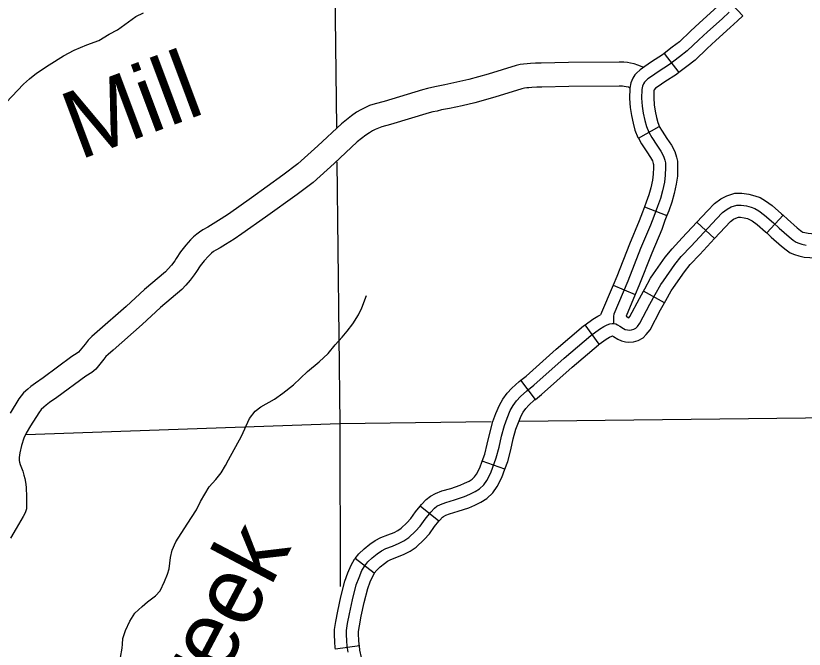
# Model space of a CAD drawing. Extents: x -3711 to 825, y -151 to 1050.
# Drawn here: x -2798.1 to -2743.1, y 424.3 to 468.5 of the extents above; entities that cross this region are included whole.
import ezdxf

# ---------------------------------------------------------------- set-up
doc = ezdxf.new("R2010")
doc.units = 0
for name, color, linetype in [('Level 32', 7, 'Continuous'), ('Level 35', 7, 'Continuous'), ('Level 46', 7, 'Continuous'), ('Level 5', 7, 'Continuous')]:
    doc.layers.add(name, color=color, linetype=linetype)

msp = doc.modelspace()

# ---------------------------------------------------------------- linework, layer by layer
at = {"layer": 'Level 32'}
for p, q in [((-2748.496, 469.762), (-2747.349, 468.533)), ((-2752.858, 465.892), (-2751.836, 464.557)), ((-2754.647, 459.97), (-2753.188, 460.804)), ((-2754.23, 455.177), (-2752.658, 454.58)), ((-2745.687, 453.356), (-2744.543, 454.589)), ((-2749.334, 452.961), (-2750.566, 454.106)), ((-2756.417, 449.713), (-2754.868, 449.059)), ((-2752.83, 448.472), (-2754.301, 449.286)), ((-2757.38, 445.58), (-2758.374, 446.936)), ((-2761.846, 441.723), (-2762.864, 443.061)), ((-2763.971, 436.847), (-2765.553, 437.414)), ((-2768.576, 433.207), (-2769.889, 434.257)), ((-2773.097, 429.573), (-2774.419, 430.611)), ((-2774.134, 424.501), (-2775.798, 424.263))]:
    msp.add_line(p, q, dxfattribs=at)
for points in [[(-2748.496, 469.762), (-2748.874, 469.409), (-2749.379, 468.944), (-2750.388, 468.032), (-2751.002, 467.459), (-2751.786, 466.714), (-2752.288, 466.327), (-2752.858, 465.892)], [(-2748.302, 468.792), (-2748.812, 468.323), (-2749.819, 467.413), (-2750.425, 466.847), (-2751.239, 466.074), (-2751.776, 465.661), (-2752.48, 465.123), (-2753.265, 464.612), (-2753.734, 464.295), (-2753.996, 464.115), (-2754.175, 463.936), (-2754.225, 463.881), (-2754.299, 463.77), (-2754.368, 463.605), (-2754.41, 463.384), (-2754.423, 462.777), (-2754.382, 462.212), (-2754.313, 461.715), (-2754.203, 461.218), (-2754.093, 460.804), (-2753.927, 460.404), (-2753.707, 460.018), (-2753.362, 459.494), (-2753.072, 459.066), (-2752.893, 458.721), (-2752.797, 458.431), (-2752.763, 458.253), (-2752.748, 458.076), (-2752.748, 457.921), (-2752.769, 457.397), (-2752.838, 456.9), (-2752.962, 456.307), (-2753.114, 455.769), (-2753.321, 455.203), (-2753.582, 454.513), (-2753.803, 453.892), (-2754.492, 452.264), (-2755.388, 449.988), (-2756.367, 447.67), (-2756.395, 447.532), (-2756.395, 447.353), (-2756.396, 447.024)], [(-2747.349, 468.533), (-2747.731, 468.176), (-2748.246, 467.702), (-2749.25, 466.794), (-2749.849, 466.235), (-2750.692, 465.435), (-2751.265, 464.994), (-2751.836, 464.557)], [(-2752.858, 465.892), (-2752.965, 465.81), (-2753.73, 465.313), (-2754.207, 464.99), (-2754.535, 464.765), (-2754.786, 464.514), (-2754.889, 464.399), (-2755.043, 464.172), (-2755.178, 463.847), (-2755.249, 463.472), (-2755.265, 462.756), (-2755.218, 462.123), (-2755.141, 461.566), (-2755.02, 461.019), (-2754.891, 460.534), (-2754.684, 460.034), (-2754.648, 459.971)], [(-2751.836, 464.557), (-2751.994, 464.435), (-2752.801, 463.911), (-2753.261, 463.6), (-2753.457, 463.466), (-2753.558, 463.365), (-2753.558, 463.363), (-2753.571, 463.297), (-2753.582, 462.798), (-2753.546, 462.3), (-2753.485, 461.864), (-2753.386, 461.418), (-2753.295, 461.074), (-2753.171, 460.775), (-2753.187, 460.804)], [(-2753.188, 460.804), (-2752.99, 460.458), (-2752.663, 459.96), (-2752.349, 459.497), (-2752.117, 459.05), (-2751.981, 458.643), (-2751.929, 458.367), (-2751.908, 458.111), (-2751.908, 457.904), (-2751.931, 457.322), (-2752.009, 456.756), (-2752.145, 456.106), (-2752.313, 455.51), (-2752.533, 454.909), (-2752.658, 454.58)], [(-2754.647, 459.97), (-2754.423, 459.578), (-2754.061, 459.027), (-2753.796, 458.635), (-2753.67, 458.392), (-2753.612, 458.219), (-2753.597, 458.14), (-2753.589, 458.041), (-2753.589, 457.938), (-2753.607, 457.471), (-2753.667, 457.044), (-2753.779, 456.507), (-2753.914, 456.027), (-2754.108, 455.497), (-2754.23, 455.177)], [(-2750.566, 454.106), (-2749.817, 454.912), (-2749.341, 455.412), (-2748.902, 455.735), (-2748.485, 455.959), (-2747.909, 456.129), (-2747.428, 456.129), (-2746.943, 456.072), (-2746.517, 455.958), (-2746.158, 455.827), (-2745.771, 455.589), (-2745.319, 455.263), (-2744.661, 454.698), (-2744.543, 454.589)], [(-2754.23, 455.177), (-2754.372, 454.803), (-2754.587, 454.197), (-2755.271, 452.582), (-2756.167, 450.305), (-2756.417, 449.713)], [(-2750.974, 452.431), (-2749.204, 454.336), (-2748.783, 454.779), (-2748.452, 455.023), (-2748.164, 455.178), (-2747.788, 455.288), (-2747.478, 455.288), (-2747.102, 455.244), (-2746.77, 455.155), (-2746.526, 455.067), (-2746.239, 454.89), (-2745.84, 454.602), (-2745.221, 454.07), (-2744.813, 453.692)], [(-2752.658, 454.58), (-2752.793, 454.223), (-2753.019, 453.587), (-2753.714, 451.946), (-2754.61, 449.67), (-2754.868, 449.059)], [(-2749.334, 452.961), (-2748.591, 453.76), (-2748.226, 454.146), (-2748.001, 454.31), (-2747.842, 454.396), (-2747.666, 454.448), (-2747.527, 454.448), (-2747.26, 454.416), (-2747.022, 454.353), (-2746.894, 454.306), (-2746.706, 454.19), (-2746.361, 453.941), (-2745.78, 453.443), (-2745.687, 453.356)], [(-2744.543, 454.589), (-2744.249, 454.315), (-2743.566, 453.711), (-2743.333, 453.519), (-2743.229, 453.45), (-2743.16, 453.419), (-2743.036, 453.381), (-2742.806, 453.332), (-2742.563, 453.306), (-2742.247, 453.291), (-2741.5, 453.26), (-2741.159, 453.26), (-2740.799, 453.217), (-2740.495, 453.156), (-2740.194, 453.076), (-2739.826, 452.947), (-2739.442, 452.801), (-2739.401, 452.781)], [(-2754.301, 449.286), (-2754.209, 449.452), (-2753.794, 450.191), (-2753.593, 450.493), (-2752.775, 451.652), (-2752.296, 452.252), (-2751.589, 453.005), (-2750.566, 454.106)], [(-2744.813, 453.692), (-2744.112, 453.072), (-2743.834, 452.843), (-2743.639, 452.713), (-2743.459, 452.631), (-2743.247, 452.566), (-2742.937, 452.501)], [(-2745.687, 453.356), (-2745.378, 453.069), (-2744.658, 452.433), (-2744.336, 452.168), (-2744.049, 451.976), (-2743.758, 451.844), (-2743.458, 451.751), (-2743.068, 451.669), (-2742.691, 451.629), (-2742.322, 451.612), (-2741.536, 451.578), (-2741.257, 451.578), (-2741.062, 451.555), (-2740.877, 451.518), (-2740.689, 451.468), (-2740.404, 451.368), (-2740.103, 451.253), (-2740.121, 451.262)], [(-2752.83, 448.472), (-2752.741, 448.634), (-2752.359, 449.312), (-2752.206, 449.542), (-2751.431, 450.642), (-2751.025, 451.15), (-2750.36, 451.858), (-2749.334, 452.961)], [(-2774.92, 424.06), (-2774.979, 424.474), (-2775.019, 424.849), (-2775.038, 425.282), (-2775.038, 425.578), (-2774.96, 426.051), (-2774.822, 426.741), (-2774.605, 427.727), (-2774.349, 428.771), (-2774.152, 429.284), (-2773.955, 429.757), (-2773.758, 430.092), (-2773.541, 430.368), (-2773.246, 430.644), (-2772.891, 430.94), (-2772.596, 431.137), (-2772.281, 431.294), (-2771.828, 431.472), (-2771.355, 431.669), (-2771.02, 431.846), (-2770.685, 432.063), (-2770.212, 432.516), (-2769.897, 432.871), (-2769.543, 433.344), (-2769.149, 433.837), (-2768.893, 434.113), (-2768.716, 434.251), (-2768.459, 434.389), (-2768.105, 434.527), (-2767.494, 434.704), (-2766.785, 434.941), (-2766.431, 435.099), (-2766.056, 435.276), (-2765.741, 435.473), (-2765.446, 435.749), (-2765.229, 436.065), (-2764.953, 436.597), (-2764.579, 437.642), (-2764.382, 438.391), (-2764.205, 439.159), (-2764.008, 439.908), (-2763.811, 440.421), (-2763.594, 440.953), (-2763.397, 441.288), (-2763.161, 441.623), (-2762.885, 441.919), (-2762.432, 442.333), (-2761.94, 442.707), (-2759.832, 444.6), (-2757.961, 446.196), (-2757.37, 446.63), (-2757.072, 446.809), (-2756.834, 446.923), (-2756.64, 446.994), (-2756.49, 447.021), (-2756.396, 447.024), (-2756.234, 446.994), (-2756.11, 446.932), (-2755.951, 446.835), (-2755.695, 446.676), (-2755.563, 446.614), (-2755.413, 446.579), (-2755.298, 446.57), (-2755.139, 446.579), (-2754.98, 446.623), (-2754.839, 446.703), (-2754.724, 446.817), (-2754.539, 447.047), (-2753.841, 448.381), (-2753.475, 449.043), (-2753.077, 449.752), (-2752.9, 450.018), (-2752.103, 451.147), (-2751.66, 451.701), (-2750.974, 452.431)], [(-2756.417, 449.713), (-2757.295, 447.634)], [(-2755.506, 447.548), (-2755.312, 447.428), (-2755.245, 447.51), (-2754.581, 448.779), (-2754.301, 449.286)], [(-2754.868, 449.059), (-2755.506, 447.548)], [(-2757.38, 445.58), (-2756.904, 445.929), (-2756.673, 446.068), (-2756.507, 446.148), (-2756.464, 446.163), (-2756.392, 446.119), (-2756.096, 445.936), (-2755.84, 445.816), (-2755.542, 445.746), (-2755.307, 445.728), (-2755.001, 445.745), (-2754.656, 445.84), (-2754.326, 446.027), (-2754.098, 446.255), (-2753.832, 446.584), (-2753.101, 447.983), (-2752.83, 448.472)], [(-2758.374, 446.936), (-2757.836, 447.331), (-2757.472, 447.549), (-2757.295, 447.634)], [(-2762.864, 443.061), (-2762.476, 443.356), (-2760.386, 445.232), (-2758.483, 446.856), (-2758.374, 446.936)], [(-2761.846, 441.723), (-2761.404, 442.059), (-2759.278, 443.967), (-2757.439, 445.537), (-2757.38, 445.58)], [(-2765.553, 437.414), (-2765.383, 437.891), (-2765.198, 438.592), (-2765.021, 439.361), (-2764.809, 440.167), (-2764.593, 440.73), (-2764.35, 441.327), (-2764.104, 441.744), (-2763.815, 442.155), (-2763.477, 442.517), (-2762.971, 442.979), (-2762.864, 443.061)], [(-2763.971, 436.847), (-2763.775, 437.392), (-2763.566, 438.189), (-2763.389, 438.958), (-2763.207, 439.65), (-2763.029, 440.112), (-2762.839, 440.58), (-2762.69, 440.832), (-2762.507, 441.092), (-2762.293, 441.321), (-2761.893, 441.687), (-2761.846, 441.723)], [(-2769.889, 434.257), (-2769.786, 434.386), (-2769.463, 434.735), (-2769.176, 434.958), (-2768.813, 435.154), (-2768.375, 435.324), (-2767.745, 435.507), (-2767.09, 435.726), (-2766.782, 435.863), (-2766.461, 436.015), (-2766.256, 436.143), (-2766.087, 436.301), (-2765.951, 436.498), (-2765.726, 436.933), (-2765.553, 437.414)], [(-2768.576, 433.207), (-2768.512, 433.288), (-2768.323, 433.492), (-2768.255, 433.544), (-2768.106, 433.624), (-2767.835, 433.73), (-2767.244, 433.902), (-2766.481, 434.156), (-2766.08, 434.335), (-2765.652, 434.537), (-2765.227, 434.804), (-2764.805, 435.198), (-2764.507, 435.632), (-2764.181, 436.26), (-2763.971, 436.847)], [(-2774.419, 430.611), (-2774.162, 430.938), (-2773.802, 431.274), (-2773.395, 431.614), (-2773.019, 431.865), (-2772.623, 432.063), (-2772.143, 432.251), (-2771.714, 432.43), (-2771.446, 432.572), (-2771.209, 432.725), (-2770.819, 433.1), (-2770.549, 433.403), (-2770.208, 433.859), (-2769.889, 434.257)], [(-2773.097, 429.573), (-2772.92, 429.798), (-2772.689, 430.013), (-2772.387, 430.265), (-2772.173, 430.408), (-2771.939, 430.526), (-2771.513, 430.692), (-2770.996, 430.908), (-2770.594, 431.121), (-2770.161, 431.401), (-2769.606, 431.933), (-2769.246, 432.339), (-2768.878, 432.83), (-2768.576, 433.207)], [(-2775.798, 424.263), (-2775.814, 424.371), (-2775.857, 424.786), (-2775.879, 425.263), (-2775.879, 425.647), (-2775.786, 426.202), (-2775.644, 426.914), (-2775.424, 427.917), (-2775.153, 429.023), (-2774.932, 429.596), (-2774.709, 430.133), (-2774.461, 430.555), (-2774.436, 430.589)], [(-2774.134, 424.501), (-2774.145, 424.577), (-2774.18, 424.912), (-2774.198, 425.301), (-2774.198, 425.508), (-2774.133, 425.9), (-2773.999, 426.568), (-2773.786, 427.536), (-2773.545, 428.519), (-2773.371, 428.971), (-2773.201, 429.381), (-2773.055, 429.629), (-2773.08, 429.595)], [(-2773.604, 418.386), (-2773.499, 418.73), (-2773.368, 419.254), (-2773.28, 419.761), (-2773.211, 420.363), (-2773.234, 420.921), (-2773.28, 421.446), (-2773.399, 421.996), (-2773.556, 422.467), (-2773.867, 423.304), (-2773.987, 423.696), (-2774.092, 424.205), (-2774.134, 424.501)]]:
    msp.add_lwpolyline(points, dxfattribs=at)
at = {"layer": 'Level 35'}
for points in [[(-2798.801, 462.465), (-2797.583, 463.747), (-2797.163, 464.125), (-2796.68, 464.525), (-2795.799, 465.113), (-2794.791, 465.722), (-2794.056, 466.121), (-2793.153, 466.5), (-2792.334, 466.815), (-2791.599, 467.235), (-2791.011, 467.55), (-2789.731, 468.475), (-2789.206, 468.727)], [(-2789.309, 427.256), (-2788.917, 427.569), (-2788.369, 428), (-2788.036, 428.353), (-2787.742, 429), (-2787.526, 429.51), (-2787.409, 429.882), (-2787.311, 430.666), (-2787.213, 431.196), (-2786.939, 431.764), (-2786.371, 432.686), (-2785.861, 433.47), (-2785.509, 433.999), (-2785.234, 434.587), (-2784.627, 435.606), (-2784.157, 436.116), (-2783.785, 436.586), (-2783.472, 437.096), (-2783.276, 437.488), (-2782.355, 439.154), (-2781.807, 440.389), (-2781.415, 440.899), (-2781.023, 441.213), (-2780.063, 441.742), (-2779.475, 442.154), (-2778.731, 442.742), (-2777.752, 443.683), (-2776.949, 444.349), (-2776.322, 444.937), (-2775.812, 445.525), (-2775.342, 446.074), (-2774.99, 446.486), (-2774.578, 447.015), (-2774.187, 447.642), (-2773.952, 448.132), (-2773.638, 448.995)], [(-2790.817, 423.688), (-2790.7, 424.335), (-2790.68, 424.609), (-2790.66, 425.021), (-2790.465, 425.57), (-2790.151, 426.217), (-2789.799, 426.785), (-2789.309, 427.256)]]:
    msp.add_lwpolyline(points, dxfattribs=at)
at = {"layer": 'Level 46'}
for points in [[(-2754.312, 464.936), (-2754.38, 464.972), (-2754.68, 465.087), (-2754.937, 465.166), (-2755.2, 465.218), (-2755.42, 465.256), (-2755.675, 465.283), (-2756.004, 465.283), (-2759.53, 465.262), (-2761.428, 465.229), (-2761.825, 465.218), (-2762.178, 465.196), (-2762.425, 465.184), (-2762.665, 465.157), (-2762.903, 465.12), (-2763.188, 465.065), (-2765.147, 464.46), (-2766.498, 464.069), (-2767.321, 463.881), (-2768.169, 463.701), (-2768.756, 463.59), (-2769.066, 463.513), (-2769.379, 463.448), (-2769.718, 463.363), (-2772.409, 462.541), (-2773.041, 462.377), (-2773.415, 462.257), (-2773.762, 462.097), (-2774.024, 461.96), (-2774.324, 461.784), (-2774.677, 461.544), (-2775.375, 460.986), (-2777.033, 459.447), (-2778.437, 458.189), (-2779.481, 457.395), (-2781.673, 455.815), (-2783.276, 454.67), (-2783.78, 454.341), (-2784.35, 453.993), (-2784.721, 453.77), (-2785.051, 453.576), (-2785.285, 453.42), (-2785.487, 453.269), (-2785.706, 453.093), (-2785.914, 452.872), (-2786.25, 452.5), (-2786.628, 452.024), (-2786.922, 451.565), (-2787.028, 451.397), (-2787.254, 451.115), (-2787.483, 450.838), (-2787.68, 450.641), (-2789.134, 449.4), (-2790.424, 448.217), (-2792.432, 446.434), (-2792.809, 446.111), (-2793.07, 445.864), (-2793.289, 445.594), (-2793.742, 445.033), (-2793.828, 444.963), (-2794.198, 444.716), (-2796.218, 443.224), (-2796.752, 442.865), (-2797.066, 442.625), (-2797.28, 442.435), (-2797.578, 442.177), (-2797.903, 441.753), (-2798.524, 440.76)], [(-2755.261, 463.507), (-2755.349, 463.534), (-2755.503, 463.564), (-2755.654, 463.59), (-2755.767, 463.602), (-2755.999, 463.602), (-2759.51, 463.581), (-2761.39, 463.548), (-2761.749, 463.538), (-2762.086, 463.517), (-2762.292, 463.507), (-2762.441, 463.491), (-2762.614, 463.463), (-2762.781, 463.431), (-2764.665, 462.849), (-2766.077, 462.44), (-2766.96, 462.239), (-2767.839, 462.052), (-2768.396, 461.947), (-2768.691, 461.873), (-2769.004, 461.809), (-2769.269, 461.742), (-2771.953, 460.922), (-2772.573, 460.762), (-2772.803, 460.688), (-2773.018, 460.588), (-2773.209, 460.488), (-2773.427, 460.361), (-2773.678, 460.191), (-2774.276, 459.712), (-2775.9, 458.205), (-2777.366, 456.892), (-2778.481, 456.044), (-2780.693, 454.449), (-2782.328, 453.282), (-2782.882, 452.92), (-2783.478, 452.555), (-2783.863, 452.324), (-2784.158, 452.151), (-2784.313, 452.048), (-2784.457, 451.94), (-2784.561, 451.856), (-2784.677, 451.732), (-2784.967, 451.412), (-2785.258, 451.046), (-2785.504, 450.663), (-2785.657, 450.42), (-2785.949, 450.054), (-2786.238, 449.705), (-2786.538, 449.405), (-2788.02, 448.14), (-2789.298, 446.968), (-2791.328, 445.166), (-2791.684, 444.861), (-2791.833, 444.72), (-2791.982, 444.536), (-2792.543, 443.844), (-2792.824, 443.612), (-2793.231, 443.34), (-2795.248, 441.851), (-2795.772, 441.497), (-2795.997, 441.326), (-2796.172, 441.171), (-2796.349, 441.018), (-2796.52, 440.794), (-2797.087, 439.886), (-2797.403, 439.352), (-2797.558, 439.008), (-2797.717, 438.504), (-2797.834, 437.994), (-2797.893, 437.667), (-2797.893, 437.59), (-2797.886, 437.457), (-2797.862, 437.335), (-2797.817, 437.177), (-2797.634, 436.702), (-2797.556, 436.43), (-2797.494, 436.196), (-2797.439, 435.934), (-2797.399, 435.598), (-2797.364, 434.9), (-2797.364, 434.609), (-2797.364, 434.329), (-2797.384, 434.066), (-2797.467, 433.791), (-2797.6, 433.541), (-2798.095, 432.693), (-2798.492, 432.021)]]:
    msp.add_lwpolyline(points, dxfattribs=at)
at = {"layer": 'Level 5'}
for points in [[(-2776.094, 491.448), (-2775.738, 460.716)], [(-2775.71, 458.325), (-2775.498, 440.02), (-2775.478, 428.638)], [(-2715.415, 440.726), (-2717.01, 440.716), (-2762.947, 440.169)], [(-2764.921, 440.146), (-2775.498, 440.02), (-2797.415, 439.252)]]:
    msp.add_lwpolyline(points, dxfattribs=at)

# ---------------------------------------------------------------- texts
at = {"layer": 'Level 35'}
for s, rotation, p in [('Mill', 20.5069, (-2793.677, 458.44)), ('Creek', 62.214, (-2786.734, 416.437))]:
    msp.add_text(s, height=4.7343, rotation=rotation, dxfattribs=at).set_placement(p)

doc.saveas('drawing.dxf')
